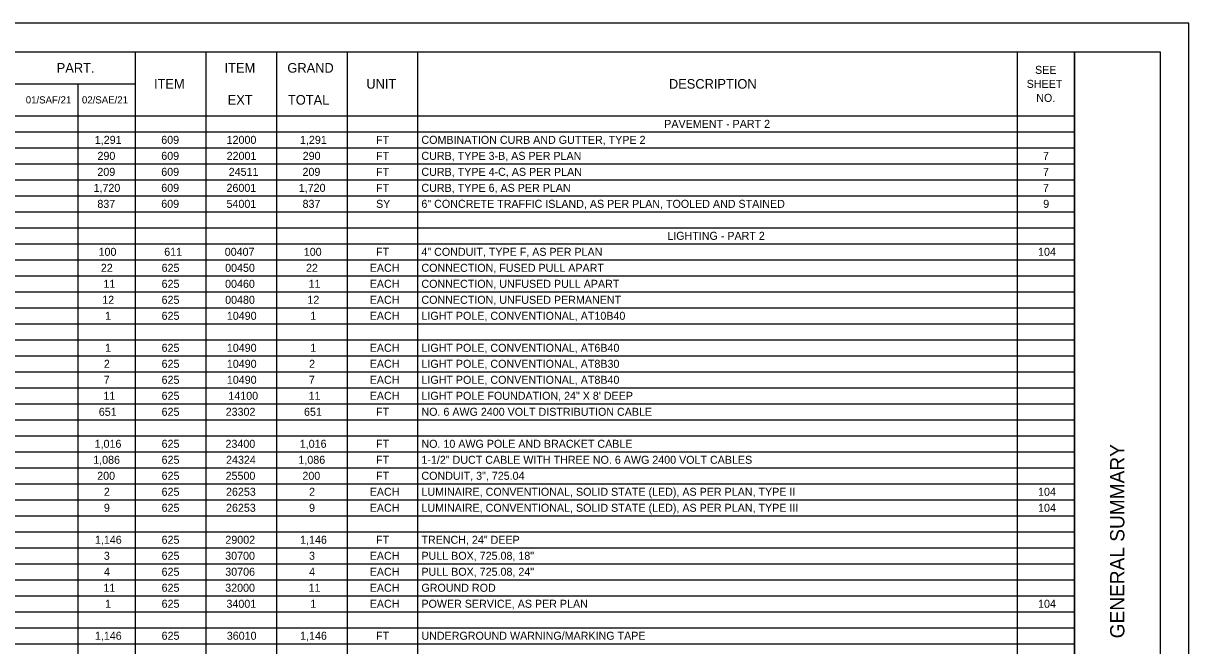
# Model space of a CAD drawing. Extents: x 0 to 76.3, y 0 to 22.
# Drawn here: x 13.61 to 34, y 11.11 to 22 of the extents above; entities that cross this region are included whole.
import ezdxf

# ---------------------------------------------------------------- set-up
doc = ezdxf.new("R2010")
doc.units = 0
for name, color, linetype in [('Default', 7, 'Continuous'), ('SH_Border', 7, 'Continuous'), ('SH_Cut_Line', 7, 'Continuous'), ('SH_Data', 7, 'Continuous')]:
    doc.layers.add(name, color=color, linetype=linetype)

msp = doc.modelspace()

# ---------------------------------------------------------------- linework, layer by layer
at = {"layer": 'Default'}
for p, q in [((1.5, 21.5), (32.004, 21.5)), ((15.566, 21.5), (15.566, 0.5)), ((16.801, 21.5), (16.801, 0.5)), ((18.036, 21.5), (18.036, 0.5)), ((19.272, 21.5), (19.272, 0.5)), ((20.507, 21.5), (20.507, 0.5)), ((30.999, 21.5), (30.999, 0.5)), ((32.004, 21.5), (32.004, 0.5)), ((1.5, 20.94), (15.566, 20.94)), ((14.561, 20.94), (14.561, 0.5)), ((1.5, 20.38), (32.004, 20.38)), ((1.5, 20.1), (32.004, 20.1)), ((1.5, 19.82), (32.004, 19.82)), ((1.5, 19.54), (32.004, 19.54)), ((1.5, 19.26), (32.004, 19.26)), ((1.5, 18.98), (32.004, 18.98)), ((1.5, 18.7), (32.004, 18.7)), ((1.5, 18.42), (32.004, 18.42)), ((1.5, 18.14), (32.004, 18.14)), ((1.5, 17.86), (32.004, 17.86)), ((1.5, 17.58), (32.004, 17.58)), ((1.5, 17.3), (32.004, 17.3)), ((1.5, 17.02), (32.004, 17.02)), ((1.5, 16.74), (32.004, 16.74)), ((1.5, 16.46), (32.004, 16.46)), ((1.5, 16.18), (32.004, 16.18)), ((1.5, 15.9), (32.004, 15.9)), ((1.5, 15.62), (32.004, 15.62)), ((1.5, 15.34), (32.004, 15.34)), ((1.5, 15.06), (32.004, 15.06)), ((1.5, 14.78), (32.004, 14.78)), ((1.5, 14.5), (32.004, 14.5)), ((1.5, 14.22), (32.004, 14.22)), ((1.5, 13.94), (32.004, 13.94)), ((1.5, 13.66), (32.004, 13.66)), ((1.5, 13.38), (32.004, 13.38)), ((1.5, 13.1), (32.004, 13.1)), ((1.5, 12.82), (32.004, 12.82)), ((1.5, 12.54), (32.004, 12.54)), ((1.5, 12.26), (32.004, 12.26)), ((1.5, 11.98), (32.004, 11.98)), ((1.5, 11.7), (32.004, 11.7)), ((1.5, 11.42), (32.004, 11.42)), ((1.5, 11.14), (32.004, 11.14))]:
    msp.add_line(p, q, dxfattribs=at)
at = {"layer": 'SH_Border'}
msp.add_line((32, 0.5), (32, 21.5), dxfattribs=at)
msp.add_lwpolyline([(1.5, 21.5), (33.5, 21.5), (33.5, 0.5), (1.5, 0.5)], close=True, dxfattribs=at)
at = {"layer": 'SH_Cut_Line'}
msp.add_lwpolyline([(0, 0), (34, 0), (34, 22), (0, 22)], close=True, dxfattribs=at)

# ---------------------------------------------------------------- texts
at = {"layer": 'Default'}
for s, height, p in [('PART.', 0.168, (14.191, 21.136)), ('ITEM', 0.168, (17.128, 21.136)), ('GRAND', 0.168, (18.227, 21.136)), ('SEE ', 0.14, (31.311, 21.115)), ('ITEM', 0.168, (15.893, 20.856)), ('UNIT', 0.168, (19.61, 20.856)), ('DESCRIPTION', 0.168, (24.904, 20.856)), ('SHEET ', 0.14, (31.165, 20.87)), ('01/SAF/21', 0.126, (13.649, 20.597)), ('02/SAE/21', 0.126, (14.632, 20.597)), ('EXT', 0.168, (17.183, 20.576)), ('TOTAL', 0.168, (18.237, 20.576)), ('NO.', 0.14, (31.332, 20.625)), ('PAVEMENT - PART 2', 0.14, (24.822, 20.17)), ('1,291', 0.14, (14.857, 19.89)), ('609', 0.14, (16.02, 19.89)), ('12000', 0.14, (17.164, 19.89)), ('1,291', 0.14, (18.448, 19.89)), ('FT', 0.14, (19.779, 19.89)), ('COMBINATION CURB AND GUTTER, TYPE 2', 0.14, (20.573, 19.89)), ('290', 0.14, (14.904, 19.61)), ('609', 0.14, (16.02, 19.61)), ('22001', 0.14, (17.164, 19.61)), ('290', 0.14, (18.495, 19.61)), ('FT', 0.14, (19.779, 19.61)), ('CURB, TYPE 3-B, AS PER PLAN', 0.14, (20.573, 19.61)), ('7', 0.14, (31.45, 19.61)), ('209', 0.14, (14.902, 19.33)), ('609', 0.14, (16.02, 19.33)), ('24511', 0.14, (17.2, 19.33)), ('209', 0.14, (18.492, 19.33)), ('FT', 0.14, (19.779, 19.33)), ('CURB, TYPE 4-C, AS PER PLAN', 0.14, (20.573, 19.33)), ('7', 0.14, (31.45, 19.33)), ('1,720', 0.14, (14.835, 19.05)), ('609', 0.14, (16.02, 19.05)), ('26001', 0.14, (17.162, 19.05)), ('1,720', 0.14, (18.426, 19.05)), ('FT', 0.14, (19.779, 19.05)), ('CURB, TYPE 6, AS PER PLAN', 0.14, (20.573, 19.05)), ('7', 0.14, (31.45, 19.05)), ('837', 0.14, (14.902, 18.77)), ('609', 0.14, (16.02, 18.77)), ('54001', 0.14, (17.162, 18.77)), ('837', 0.14, (18.493, 18.77)), ('SY', 0.14, (19.779, 18.77)), ('6" CONCRETE TRAFFIC ISLAND, AS PER PLAN, TOOLED AND STAINED', 0.14, (20.573, 18.77)), ('9', 0.14, (31.454, 18.77)), ('LIGHTING - PART 2', 0.14, (24.876, 18.21)), ('100', 0.14, (14.923, 17.93)), ('611', 0.14, (16.072, 17.93)), ('00407', 0.14, (17.131, 17.93)), ('100', 0.14, (18.514, 17.93)), ('FT', 0.14, (19.779, 17.93)), ('4" CONDUIT, TYPE F, AS PER PLAN', 0.14, (20.573, 17.93)), ('104', 0.14, (31.364, 17.93)), ('22', 0.14, (14.963, 17.65)), ('625', 0.14, (16.026, 17.65)), ('00450', 0.14, (17.138, 17.65)), ('22', 0.14, (18.553, 17.65)), ('EACH', 0.14, (19.668, 17.65)), ('CONNECTION, FUSED PULL APART', 0.14, (20.573, 17.65)), ('11', 0.14, (15.008, 17.37)), ('625', 0.14, (16.026, 17.37)), ('00460', 0.14, (17.137, 17.37)), ('11', 0.14, (18.598, 17.37)), ('EACH', 0.14, (19.668, 17.37)), ('CONNECTION, UNFUSED PULL APART', 0.14, (20.573, 17.37)), ('12', 0.14, (14.987, 17.09)), ('625', 0.14, (16.026, 17.09)), ('00480', 0.14, (17.138, 17.09)), ('12', 0.14, (18.577, 17.09)), ('EACH', 0.14, (19.668, 17.09)), ('CONNECTION, UNFUSED PERMANENT', 0.14, (20.573, 17.09)), ('1', 0.14, (15.037, 16.81)), ('625', 0.14, (16.026, 16.81)), ('10490', 0.14, (17.168, 16.81)), ('1', 0.14, (18.628, 16.81)), ('EACH', 0.14, (19.668, 16.81)), ('LIGHT POLE, CONVENTIONAL, AT10B40', 0.14, (20.573, 16.81)), ('1', 0.14, (15.037, 16.25)), ('625', 0.14, (16.026, 16.25)), ('10490', 0.14, (17.168, 16.25)), ('1', 0.14, (18.628, 16.25)), ('EACH', 0.14, (19.668, 16.25)), ('LIGHT POLE, CONVENTIONAL, AT6B40', 0.14, (20.573, 16.25)), ('2', 0.14, (15.016, 15.97)), ('625', 0.14, (16.026, 15.97)), ('10490', 0.14, (17.168, 15.97)), ('2', 0.14, (18.607, 15.97)), ('EACH', 0.14, (19.668, 15.97)), ('LIGHT POLE, CONVENTIONAL, AT8B30', 0.14, (20.573, 15.97)), ('7', 0.14, (15.012, 15.69)), ('625', 0.14, (16.026, 15.69)), ('10490', 0.14, (17.168, 15.69)), ('7', 0.14, (18.603, 15.69)), ('EACH', 0.14, (19.668, 15.69)), ('LIGHT POLE, CONVENTIONAL, AT8B40', 0.14, (20.573, 15.69)), ('11', 0.14, (15.008, 15.41)), ('625', 0.14, (16.026, 15.41)), ('14100', 0.14, (17.194, 15.41)), ('11', 0.14, (18.598, 15.41)), ('EACH', 0.14, (19.668, 15.41)), ('LIGHT POLE FOUNDATION, 24" X 8\' DEEP', 0.14, (20.573, 15.41)), ('651', 0.14, (14.927, 15.13)), ('625', 0.14, (16.026, 15.13)), ('23302', 0.14, (17.147, 15.13)), ('651', 0.14, (18.518, 15.13)), ('FT', 0.14, (19.779, 15.13)), ('NO. 6 AWG 2400 VOLT DISTRIBUTION CABLE', 0.14, (20.573, 15.13)), ('1,016', 0.14, (14.854, 14.57)), ('625', 0.14, (16.026, 14.57)), ('23400', 0.14, (17.144, 14.57)), ('1,016', 0.14, (18.444, 14.57)), ('FT', 0.14, (19.779, 14.57)), ('NO. 10 AWG POLE AND BRACKET CABLE', 0.14, (20.573, 14.57)), ('1,086', 0.14, (14.829, 14.29)), ('625', 0.14, (16.026, 14.29)), ('24324', 0.14, (17.154, 14.29)), ('1,086', 0.14, (18.42, 14.29)), ('FT', 0.14, (19.779, 14.29)), ('1-1/2" DUCT CABLE WITH THREE NO. 6 AWG 2400 VOLT CABLES', 0.14, (20.573, 14.29)), ('200', 0.14, (14.899, 14.01)), ('625', 0.14, (16.026, 14.01)), ('25500', 0.14, (17.146, 14.01)), ('200', 0.14, (18.49, 14.01)), ('FT', 0.14, (19.779, 14.01)), ('CONDUIT, 3", 725.04', 0.14, (20.573, 14.01)), ('2', 0.14, (15.016, 13.73)), ('625', 0.14, (16.026, 13.73)), ('26253', 0.14, (17.153, 13.73)), ('2', 0.14, (18.607, 13.73)), ('EACH', 0.14, (19.668, 13.73)), ('LUMINAIRE, CONVENTIONAL, SOLID STATE (LED), AS PER PLAN, TYPE II', 0.14, (20.573, 13.73)), ('104', 0.14, (31.364, 13.73)), ('9', 0.14, (15.016, 13.45)), ('625', 0.14, (16.026, 13.45)), ('26253', 0.14, (17.153, 13.45)), ('9', 0.14, (18.607, 13.45)), ('EACH', 0.14, (19.668, 13.45)), ('LUMINAIRE, CONVENTIONAL, SOLID STATE (LED), AS PER PLAN, TYPE III', 0.14, (20.573, 13.45)), ('104', 0.14, (31.364, 13.45)), ('1,146', 0.14, (14.859, 12.89)), ('625', 0.14, (16.026, 12.89)), ('29002', 0.14, (17.142, 12.89)), ('1,146', 0.14, (18.45, 12.89)), ('FT', 0.14, (19.779, 12.89)), ('TRENCH, 24" DEEP', 0.14, (20.573, 12.89)), ('3', 0.14, (15.015, 12.61)), ('625', 0.14, (16.026, 12.61)), ('30700', 0.14, (17.139, 12.61)), ('3', 0.14, (18.606, 12.61)), ('EACH', 0.14, (19.668, 12.61)), ('PULL BOX, 725.08, 18"', 0.14, (20.573, 12.61)), ('4', 0.14, (15.017, 12.33)), ('625', 0.14, (16.026, 12.33)), ('30706', 0.14, (17.14, 12.33)), ('4', 0.14, (18.608, 12.33)), ('EACH', 0.14, (19.668, 12.33)), ('PULL BOX, 725.08, 24"', 0.14, (20.573, 12.33)), ('11', 0.14, (15.008, 12.05)), ('625', 0.14, (16.026, 12.05)), ('32000', 0.14, (17.139, 12.05)), ('11', 0.14, (18.598, 12.05)), ('EACH', 0.14, (19.668, 12.05)), ('GROUND ROD', 0.14, (20.573, 12.05)), ('1', 0.14, (15.037, 11.77)), ('625', 0.14, (16.026, 11.77)), ('34001', 0.14, (17.161, 11.77)), ('1', 0.14, (18.628, 11.77)), ('EACH', 0.14, (19.668, 11.77)), ('POWER SERVICE, AS PER PLAN', 0.14, (20.573, 11.77)), ('104', 0.14, (31.364, 11.77)), ('1,146', 0.14, (14.859, 11.21)), ('625', 0.14, (16.026, 11.21)), ('36010', 0.14, (17.167, 11.21)), ('1,146', 0.14, (18.45, 11.21)), ('FT', 0.14, (19.779, 11.21)), ('UNDERGROUND WARNING/MARKING TAPE', 0.14, (20.573, 11.21))]:
    msp.add_text(s, height=height, dxfattribs=at).set_placement(p)
at = {"layer": 'SH_Data'}
msp.add_text('GENERAL SUMMARY', height=0.25, rotation=90, dxfattribs=at).set_placement((32.875, 11.235))

doc.saveas('drawing.dxf')
